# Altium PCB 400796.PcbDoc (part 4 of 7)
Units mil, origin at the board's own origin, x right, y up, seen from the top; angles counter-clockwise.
Board outline 2086.61 x 2086.61 mil, 6 copper layers (Top Layer, Mid Layer 1, Mid Layer 2, Mid Layer 3, Mid Layer 4, Bottom Layer), stack 58.818 mil thick; 313 components, 234 nets, 1244 pads, 2538 vias.
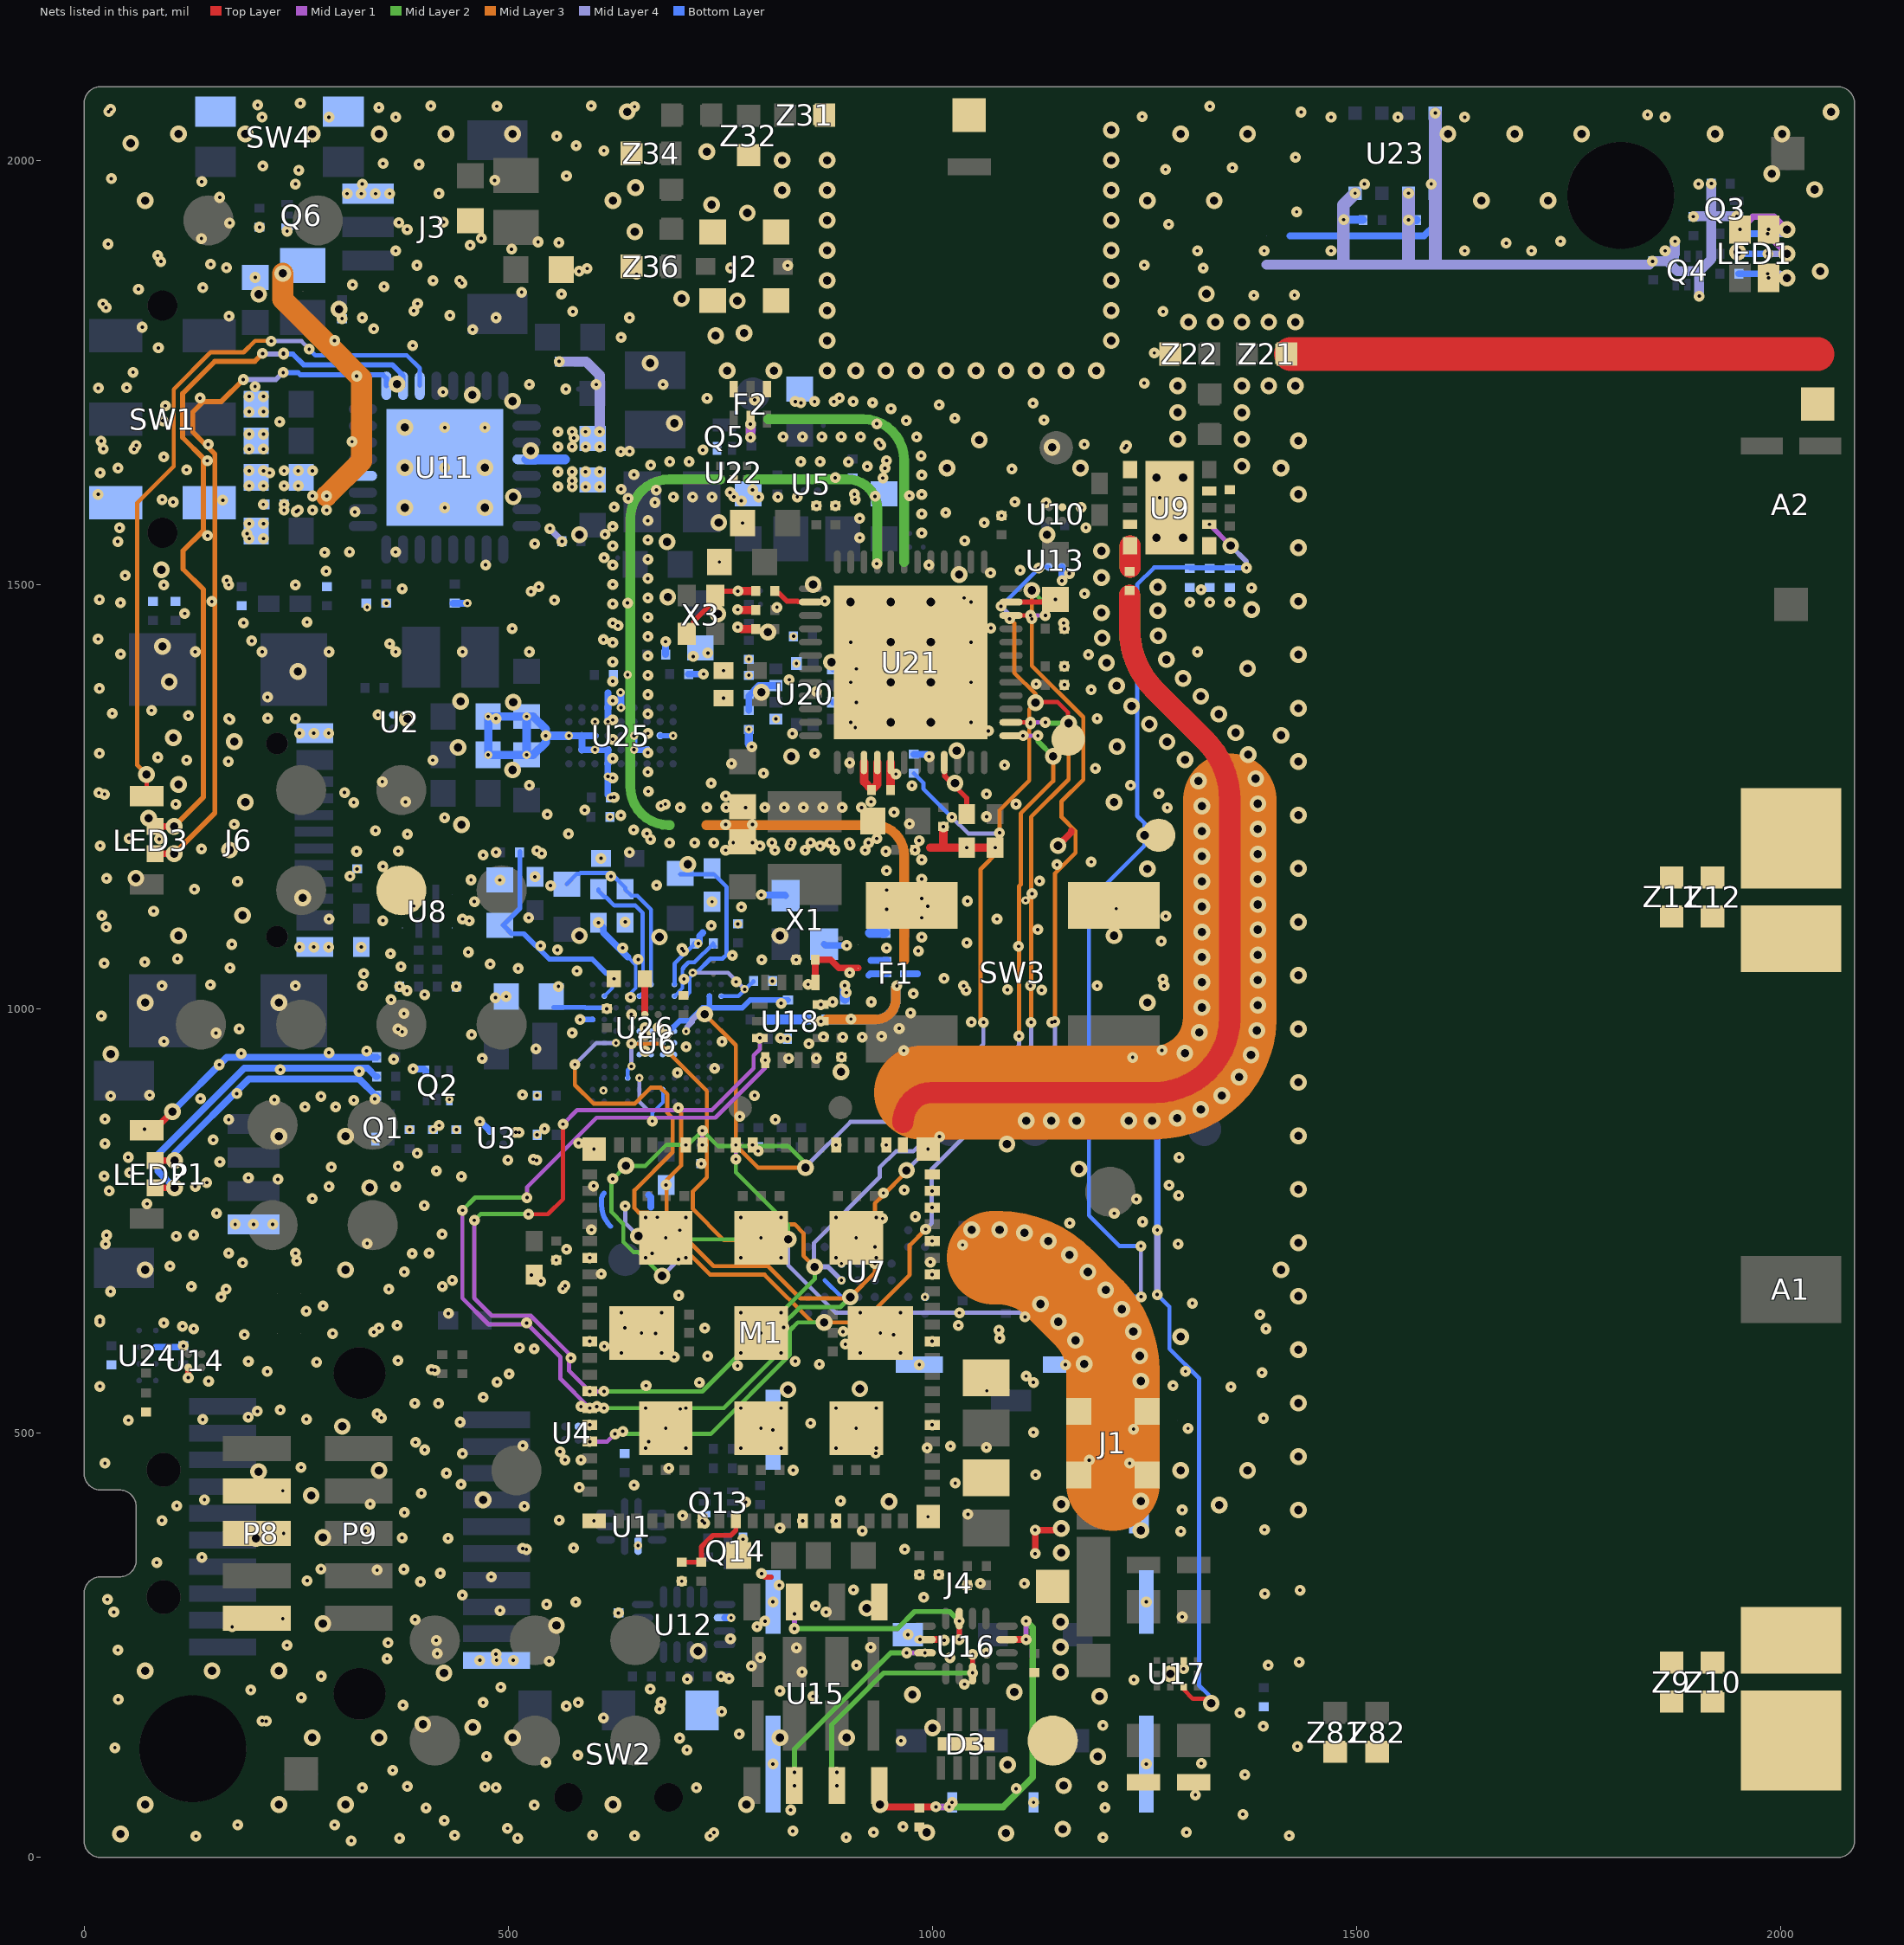
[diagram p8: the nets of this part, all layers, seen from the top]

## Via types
v1: diameter 12.8, hole 3.94, Mid Layer 4 to Bottom Layer, tented both sides, 653 vias
v2: diameter 12.8, hole 3.94, Top Layer to Mid Layer 1, tented both sides, 560 vias
v3: diameter 12.8, hole 3.94, Mid Layer 3 to Mid Layer 4, tented both sides, 388 vias
v4: diameter 19.68, hole 9.84, Mid Layer 1 to Mid Layer 4, tented both sides, 311 vias
v5: diameter 12.8, hole 3.94, Mid Layer 1 to Mid Layer 2, tented both sides, 265 vias
v6: diameter 19.68, hole 9.84, Top Layer to Bottom Layer, tented both sides, 169 vias
v7: diameter 9.84, hole 3.94, Mid Layer 4 to Bottom Layer, tented both sides, 105 vias
v8: diameter 12.8, hole 3.94, Top Layer to Mid Layer 1, tented top, 70 vias
v9: diameter 9.84, hole 3.94, Top Layer to Mid Layer 1, tented both sides, 17 vias

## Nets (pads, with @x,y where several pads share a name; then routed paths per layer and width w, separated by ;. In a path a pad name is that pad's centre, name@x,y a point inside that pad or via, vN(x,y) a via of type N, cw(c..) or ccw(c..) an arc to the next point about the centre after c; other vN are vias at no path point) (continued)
GND: C1.2 C2.2 C3.2 C4.2 C5.2 C6.2 C7.2 C8.1 C10.2 C11.1 C12.2 C13.2 C14.1 C15.2 C16.2 C17.1 C18.2 C19.2 C20.2 C21.2 C22.1 C23.1 C24.1 C25.1 C26.2 C27.2 C28.2 C29.1 C30.1 C32.1 C33.1 C34.1 C35.1 C36.1 C37.1 C38.1 C39.1 C40.1 C41.1 C42.1 C43.1 C44.1 C45.2 C46.1 C49.1 C50.1 C51.1 C54.2 C55.2 C56.1 C57.1 C58.1 C59.1 C60.1 C61.1 C62.2 C63.1 C64.1 C65.1 C66.2 C67.2 C68.1 C69.1 C70.1 C71.1 C72.1 C73.1 C75.1 C76.1 C77.1 C78.1 C79.2 C80.1 C81.1 C82.2 C83.2 C84.2 C85.2 C86.1 C87.1 C88.1 C89.1 C90.1 C91.1 C92.1 C93.1 C94.1 C95.1 C96.1 C97.1 C98.1 C99.2 C100.2 C101.1 C102.1 C103.1 CR1.1 D3.9 F1.2 F1.3 F1.5 F2.2 F2.5 F2.7 J1.2 J2.2 J3.1 J4.0 J4.C5 J4.CSW J6.A1 J6.A12 M1.1 M1.7 M1.13 M1.15 M1.20 M1.25 M1.30 M1.34 M1.36 M1.38 M1.39 M1.40 M1.41 M1.43 M1.46 M1.51 M1.55 M1.60 M1.66 M1.71 M1.76 M1.105 M1.106 M1.107 M1.108 M1.109 M1.110 M1.111 M1.112 M1.113 NT1.1 NT2.1 P1.1 P8.3 P8.5 P8.9 P9.20 Q1.2 Q2.1 Q2.4 Q3.2 Q4.1 Q4.4 Q5.2 Q6.1 Q13.1 Q14.2 R7.2 R8.2 R9.1 R11.1 R15.2 R30.1 R33.1 R38.1 R41.1 R42.1 R44.1 R45.1 R46.1 R53.1 R54.1 R58.2 R59.2 R60.1 R61.2 R64.2 SBI2.2 SW1.1 SW1.4 SW2.1 SW3.1 SW4.2 TP15.1 TP16.1 U1.6 U2.B1 U3.B1 U4.B1 U5.B1 U6.A5 U6.B2 U6.B9 U6.C2 U6.D12 U6.E5 U6.E6 U6.E7 U6.E8 U6.F5 U6.F6 U6.F7 U6.F8 U6.G5 U6.G6 U6.G7 U6.G8 U6.K6 U6.K11 U7.A2 U7.D5 U7.F4 U8.5 U8.8 U9.1 U9.4 U9.6 U9.9 U9.11 U10.B1 U11.33 U12.6 U13.B1 U14.B1 U15.1 U16.6 U17.7 U18.6 U18.7 U20.1 U20.3 U20.7 U20.11 U21.27 U21.28 U21.47 U21.49 U22.2 U23.1 U23.5 U23.7 U24.B1 U25.A3 U25.B3 U25.C2 U25.D2 U25.D3 U25.E5 U25.F1 U25.F2 U25.F4 U25.F5 U25.G2 U25.G3 U25.G4 U25.H2 U25.H3 U25.J3 U26.B1 U26.B2 U26.C3 X1.2 X1.4 X3.2 X3.4 Z6.2 Z22.2 Z32.1 Z34.2 Z36.2 | length 6211.1
  Top Layer w6: X3.4@710.43,1441.93 718.26,1449.76 718.26,1456.47 736.07,1474.28 736.07,1479.38 749.01,1492.31 v2(770.65,1492.31) ; 798.97,333.54 802.25,330.26 809.75,330.26 ; U21.47@1092.52,1479.33 1141.73,1479.33 v2(1144.68,1482.28)
  Top Layer w6.69: v2(122.81,565.43) U14.B1@122.81,577.34
  Top Layer w7.87: U16.6@991.14,256.89 v2@1013.78,256.89 ; v2(1121.06,358.09) v2(1121.06,385.83) v2(1151.77,385.83) ; v6(1147.88,1192.29) 1163.39,1207.8 1163.39,1209.65
  Top Layer w9.84: v2@770.43,1469.99 C70.1@791.73,1469.99 ; v2(770.65,1492.31) 770.88,1492.55 C69.1@791.73,1492.55 ; v2@771.56,1450.95 775.07,1447.43 C71.1@791.73,1447.43 ; C64.1@776.92,1238.08 C64.1@777.66,1237.34 ; 997.05,1189.96 1012.8,1189.96 ; v2@1012.8,1208.27 1012.8,1189.96 ; v2(1073.82,1189.96) 1012.8,1189.96
  Top Layer w10: U21.27@919.29,1290.35 919.29,1267.56 928.1,1258.75 C66.2@928.1,1258.35 ; C66.2@928.1,1257.76 C66.2@928.1,1258.35 ; U21.28@935.04,1290.35 935.04,1264.7 929.01,1258.67 928.42,1258.67 C66.2@928.1,1258.35
  Mid Layer 1 w11.81: v2(785.43,1673.23) v5(785.43,1688.98)
  Mid Layer 2 w11.42: 690.37,1216.54 689.05,1216.54 cw(c689.05,1261.74) 643.84,1261.74 643.84,1577.85 cw(c690.01,1577.85) 690.01,1624.02 750,1624.02 ; 782.48,1624.02 899.61,1624.02 cw(c899.61,1588.58) 935.04,1588.58 935.04,1526.57 ; 806.1,1694.88 918.28,1694.88 cw(c918.28,1646.63) 966.54,1646.63 966.54,1526.57
  Mid Layer 3 w11.42: 733.14,1216.54 931.09,1216.54 cw(c931.09,1181.1) 966.53,1181.1 966.53,1057.11 ; 875.24,987.41 933.22,987.41 ccw(c933.22,1010.85) 956.67,1010.85 956.67,1025.61
  Mid Layer 3 w25.12: 965.25,869.54 965.25,866.12 cw(c1001.58,866.12) 975.89,891.81 ; 1189.72,405.31 1203.3,418.89 ccw(c1180.85,441.34) 1212.6,441.34 ; 1232.28,1487.4 1232.28,1446.93 ; 1232.78,1520.67 1232.78,1545.53 ; 1232.28,1446.93 ccw(c1332.28,1446.93) 1261.57,1376.22 ; 1232.28,1446.93 ccw(c1332.28,1446.93) 1261.57,1376.22 ; 1261.57,1376.22 1321.1,1316.69 ; 1321.1,1316.69 cw(c1250.39,1245.98) 1350.39,1245.98 ccw(c1250.39,1245.98) 1321.1,1316.69
  Mid Layer 3 w110.24: 986.5,901.33 1261.45,901.33 ccw(c1261.45,990.9) 1324.78,927.57 ccw(c1262.96,989.39) 1350.39,989.39 1350.39,1245.98 ; 1071.74,706.64 1078.2,706.64 cw(c1078.2,606.64) 1148.91,677.35 1183.31,642.96 cw(c1112.6,572.24) 1212.6,572.24 1212.6,439.83
  Mid Layer 4 w4.92: v3(761.44,1608.56) 772.63,1597.37 773.45,1597.37 v1(774.71,1598.63)
  Mid Layer 4 w11.81: 1393.7,1876.97 1844.62,1876.97 v1(1848.56,1880.9) 1866.15,1880.9 ; v1(1875,1904.53) 1875,1889.76 1866.15,1880.9 ; v1@1897.24,1934.05 1917.91,1934.05 ; v1(1903.54,1839.77) 1903.54,1869.09 ; v1(1917.91,1972.44) 1917.91,1934.05 ; v1(1947.83,1934.05) 1917.91,1934.05 ; 1866.15,1880.9 1877.95,1869.09 1903.54,1869.09 ; 1903.54,1869.09 1917.91,1883.46 1917.91,1934.05
  Mid Layer 4 w15: 1484.13,1881.89 1484.13,1947.18 v1(1498.03,1961.08) ; 1561.02,1879.57 v1(1561.02,1929.6) v1(1561.02,1961.08) ; 1592.52,1879.92 v1(1592.52,2055.57)
  Bottom Layer w4.13: U6.B9@640.73,1014.96 650.28,1024.51 650.28,1051.68 640.94,1061.02 ; v1(669.81,867.68) 669.81,877.58 682.07,889.84 U6.K6@682.07,904.72
  Bottom Layer w4.92: U6.A5@695.85,1028.74 695.95,1028.84 695.95,1053.25 719.08,1076.38 C28.2@719.08,1076.97 ; v1(731.3,394) Q13.1@731.3,404.53
  Bottom Layer w5: 873.03,680.12 892.72,660.43
  Bottom Layer w5.91: U25.B3@678.94,1321.85 v7(694.29,1321.85) U25.A3@694.56,1322.12
  Bottom Layer w6: 613.02,782.73 ccw(c620.45,775.29) 609.94,775.29 609.94,769.29 ccw(c646.05,769.29) 620.51,743.76
  Bottom Layer w6.69: v1(584.63,987.4) U6.D12@599.39,987.4 ; v1@688.96,969.69 688.96,972.85 702.13,986.01 714,986.01 729.16,1001.18 U6.C2@737.19,1001.18 ; U6.B2@737.19,1014.96 U6.C2@737.19,1001.18 ; C24.1@829.71,1010.43 785.07,1010.43 775.81,1001.18 U6.C2@737.19,1001.18
  Bottom Layer w7.87: U24.B1@84.65,601.38 115.75,601.38 v1(117.13,602.76) ; v1(387.8,929.13) 400.41,929.13 Q2.1@403,926.55 ; C79.2@435.04,1477.95 v7(451.77,1477.95) ; v1(466.54,867.13) 467.52,867.13 U3.B1@478.35,856.3 ; v7(571.46,1321.85) U25.H3@586.81,1321.85 ; U25.G3@602.17,1321.85 U25.H3@586.81,1321.85 ; v1(606.28,1101.57) 612.19,1095.67 612.19,1089.77 640.94,1061.02 ; U25.F1@617.37,1288.63 617.37,1252.12 v7(620.47,1249.02) ; U25.F1@617.52,1288.78 U25.F2@617.52,1305.32 v7(602.17,1305.32) U25.H2@586.81,1305.32 U25.H3@586.81,1321.85 ; v7(617.52,1338.39) U25.F5@617.52,1354.92 617.52,1372.64 ; v7(632.87,1354.92) v7@632.87,1372.32 ; v7(648.23,1321.85) v7(648.23,1305.32) U25.C2@663.58,1305.32 ; 665.53,780.64 668.01,778.16 668.01,766.49 ; R9.1@685.43,1417.32 v1(685.43,1432.68) ; C85.2@712.46,1394.5 v1(730.13,1394.5) ; v7(724,1076.97) 725.38,1078.35 725.38,1085.83 729.31,1089.76 ; U12.6@754.92,282.48 755.02,282.38 v7(762.63,282.38) ; v1(798.21,1134.2) 826.04,1134.2 X1.2@826.96,1133.28 ; U5.B1@864.61,1625.93 v1@886.26,1625.93 ; X1.4@872.23,1076.19 873.82,1074.61 v1(898.97,1074.61) ; U20.3@883.27,1361.22 v1(910.43,1361.22) ; U20.1@883.27,1400.59 v1(910.43,1400.59) ; 924.76,1039.41 926.71,1041.36 F1.2@946.84,1041.36 ; 927.37,1057.13 F1.3@945.57,1057.13 ; CR1.1@943.11,1089.61 CR1.1@946.01,1089.61 ; F1.3@945.59,1057.11 F1.3@946.84,1057.11 ; F1.5@966.53,1041.36 982.39,1041.36 ; R53.1@978.01,1299.93 993.38,1299.93 v1(996.06,1297.24) ; v7@1108.8,1127.81 v7(1109.65,1127.81) ; v1(1152.56,1504.52) U13.B1@1152.56,1520.8 ; Q4.4@1875.98,1886.81 v1@1875.98,1903.54 ; v1(1903.54,1839.77) Q4.1@1903.54,1853.35
  Bottom Layer w9.84: C80.1@521.65,1299.32 v7(521.65,1299.21) ; v7(571.46,1321.85) v1(544.19,1321.85) ; v1@1561.04,1929.58 C56.1@1570.43,1929.58 ; v7(521.65,1299.21) 529.53,1299.21 544.19,1313.87 v1(544.19,1321.85) ; v7(521.65,1299.21) v7(476.38,1299.21) v7(476.38,1344.49) v7(521.65,1344.49) ; v7(521.65,1299.21) v7(521.65,1344.49) ; v7(521.65,1344.49) 529.53,1344.49 544.19,1329.83 v1(544.19,1321.85)
  Bottom Layer w10: v7(783.46,1329.33) 783.46,1312.37 v1(787.02,1308.81) ; v1(1484.61,1929.9) C57.1@1507.17,1929.9
  Bottom Layer w11.81: C25.1@896.64,1011.81 v1(896.65,1027.56) ; 926.38,1089.61 CR1.1@943.11,1089.61
  other v1: 314.96,19.68 898.25,23.79 1420.28,25.59 436.84,26.19 599.39,26.19 742.29,29.31 1299.21,29.53 181.1,38.39 295.28,38.39 1023.03,64.96 1119.09,64.96 1309.78,73.7 363.83,102.63 812.01,110.24 1251.97,110.24 1316.77,110.88 544.42,112.12 1430.12,130.91 772.08,145.38 1389.76,154.53 1362.2,170.28 678.32,174.91 582.47,182.6 256.02,188.46 491.14,200.79 1237.23,209.48 846.27,218.62 786.42,225.39 910.43,226.38 1395.65,226.48 1432.09,230.32 548.23,231.3 466.54,232.28 486.22,232.28 505.91,232.28 416.34,240.16 971.06,262.6 390.09,280.29 1294.29,283.46 629.92,288.19 862.18,296.5 545.28,298.23 579.47,301.04 812.01,301.18 1251.97,301.18 27.56,304.13 1391.63,310.91 906.81,315.26 1433.07,314.96 419.85,334.98 345.47,338.58 279.24,339.96 85.63,347.44 776.57,375 374.9,376.61 429.13,375.98 1292.62,384.25 331.69,384.84 917.32,384.84 1391.26,386.2 560.02,397.65 705.51,402.92 1294.29,409.45 109.25,414.37 583.77,436 427.17,452.76 689.22,458.75 24.61,464.57 1232.28,464.57 566.93,468.5 585.63,468.5 1184.7,468.1 933.07,476.38 401.57,480.32 665.35,490.16 812.01,503.94 1236.89,504.64 856.3,511.81 52.4,515.25 1389.99,517.55 345.47,522.64 231.38,527.35 702.76,528.54 585.63,531.5 604.33,531.5 470.47,542.32 18.7,555.12 662.4,556.1 1283.46,556.1 146.81,561.38 1110.36,567.33 500.98,569.88 1388.23,571.31 409.45,574.8 984.45,580.71 1156.68,580.71 838.17,584.74 573.82,588.58 695.57,589.71 530.51,599.41 613.19,602.36 897.19,604.86 188.98,616.14 341.54,619.09 637.57,624.25 116.14,625.98 369.09,626.97 1030.51,626.97 521.65,629.92 18.7,630.91 1385.97,639.62 1306.29,653.06 161.42,660.43 564.17,670.33 538.39,679.13 434.06,680.12 101.38,696.85 187.01,700.79 997.46,701.62 386.81,711.61 669.44,711.97 1035.43,721.85 333.66,723.43 1289.42,722.95 26.57,733.27 129.26,733.66 598.07,739.64 702.34,739.13 178.15,746.06 199.8,746.06 222.44,746.06 941.1,752.94 675.66,754.46 979.66,755.19 1214.2,759.01 400.99,768.39 74.25,770.23 1240.32,775.64 1290.14,780.12 942.19,783.04 966.73,786.36 686.01,792.52 144.68,795.28 623.12,799.72 23.78,802.91 291.48,813.39 370.32,814.39 727.38,817.52 529.42,822.73 52.09,825.07 1290.58,824.96 794.64,832.4 152.23,845.62 512.8,854.33 71.34,858.24 24.61,870.08 224.41,892.72 317.96,892.24 516.79,898.82 830.59,941.68 863.13,941.68 1235.92,942.78 661.4,950 688.96,950 966.12,950.73 1270.34,951.06 854.31,958.86 894.31,966.67 917.11,966.67 871.52,966.95 939.88,967.64 456.69,969.49 661.4,969.69 685.96,969.69 960.73,976.87 377.05,994.5 974.1,995.33 882.31,1008.14 927.9,1008.14 361.85,1010.8 497.52,1014.47 977.4,1017.88 1039.7,1021.83 1088.33,1022.61 1128.59,1022.08 372.03,1026.38 438.65,1026.38 853.33,1028.74 1271.46,1034.89 1013.66,1035.81 329.72,1041.34 361.22,1064.96 452.89,1066.8 704.72,1070.87 945.8,1071.66 634.84,1071.85 253.94,1072.83 270.87,1072.83 288.39,1072.83 326.77,1072.83 1101.4,1073.63 1040.48,1077.91 1269.68,1079.72 987.26,1084.49 1124.02,1093.5 739.31,1097.95 637.8,1102.36 454.06,1103.74 352.27,1103.91 987.26,1107.29 945.8,1117.25 1216.54,1118.11 774.65,1119.98 460.08,1126.3 740.14,1126.18 1041.21,1126.97 987.26,1130.08 945.8,1140.05 1126.06,1150.53 456.12,1151.99 490.14,1151.77 987.26,1152.88 531.48,1155.71 945.8,1162.84 352.17,1167.8 1146.65,1169.96 987.26,1175.68 609.23,1177.36 470.32,1181.13 539.37,1183.07 321.24,1185.61 945.1,1185.63 370.31,1185.94 719.55,1195.81 742.34,1195.81 765.14,1195.81 787.93,1195.81 810.73,1195.81 833.52,1195.81 856.32,1195.81 879.11,1195.81 901.91,1195.81 924.7,1195.81 984.26,1198.27 571.09,1206.17 663.39,1206.69 972.94,1218.06 425.06,1225.27 1063.71,1226.44 954.63,1231.64 733.96,1237.27 756.76,1237.27 779.55,1237.27 802.35,1237.27 825.15,1237.27 847.94,1237.27 870.74,1237.27 893.53,1237.27 916.33,1237.27 685.04,1241.14 1098.43,1241.21 1266.73,1253.94 307.09,1254.92 739.17,1265.75 956.95,1276.69 800.83,1277.51 1191.93,1283.46 1084.86,1287.23 861.22,1301.18 253.94,1324.8 270.87,1324.8 288.39,1324.8 1115.34,1335.99 216.54,1342.52 346.46,1346.46 1187.01,1375.98 1122.15,1382.72 717.97,1415.25 1183.68,1417.29 735.24,1419.25 360.24,1430.12 612.2,1435.04 629.33,1451.38 187.99,1454.72 1154.55,1454.65 262.8,1455.71 1117.13,1459.65 816.62,1473.21 43.02,1478.51 1303.15,1478.94 1326.77,1478.94 1350.39,1478.94 150.6,1479.94 873.07,1480.43 1037.4,1484.25 1179.1,1489.11 375,1495.08 1375.98,1496.06 94.03,1499.44 168.31,1504.92 285.43,1515.75 1103.35,1516.73 612.94,1531.5 283.51,1537.75 312.99,1538.39 39.79,1550.65 194.64,1554.13 211.47,1554.13 145.69,1557.55 1180.73,1567 194.64,1571.85 211.47,1571.85 1061.02,1572.83 1015.54,1584.75 425.2,1590.55 211.34,1594.38 1133.92,1596.28 92.14,1600.01 972.77,1604.62 907.94,1606.5 787.9,1611.45 194.64,1616.33 211.47,1616.33 885.38,1625.93 19.09,1631.71 194.64,1634.05 211.47,1634.05 1093.51,1636.08 943.93,1637.15 425.2,1637.8 145.42,1645.96 94,1650.3 729.33,1658.46 58.98,1659.59 194.64,1659.54 211.47,1659.54 22.77,1659.79 1178.9,1665.2 194.64,1677.26 211.47,1677.26 425.2,1685.04 472.44,1685.04 934.32,1689.45 92.91,1693.06 1131.33,1693.87 1026.27,1695.85 194.64,1703.74 211.47,1703.74 734.33,1719.49 194.64,1721.46 211.47,1721.46 567.91,1730.32 295.28,1787.4 341.54,1801.26 304.16,1813.32 431.25,1817.02 393.11,1830.98 353.65,1851.05 316.49,1853.21 442.66,1858.18 201.8,1861.89 651.16,1865.77 583.44,1869.14 167.88,1873.21 392.37,1876.17 86.84,1887.64 535.11,1903.7 138.38,1907.63 468.23,1907.92 239.34,1916.43 380.91,1918.31 206.85,1921.04 171.64,1925.99 1896.65,1933.46 159.91,1956.23 310.04,1960.63 326.77,1960.63 343.5,1960.63 360.24,1960.63 418.25,1960.84 483.97,1976.2 568.55,1981.54 252.95,1988.19 210.63,1993.11 394.81,1994.99 352.36,1996.06 612.66,2011.25 557.06,2028.27 31.5,2060.04 347.44,2062.01 486.5,2063.59 648.91,2063.03 408.66,2063.87 597.77,2064.15 204.72,2064.96 254.92,2066.93
  other v2: 371.84,22.76 511.01,22.76 1200.79,23.62 131.96,25.2 648.84,25.6 737.72,25.28 930.5,29.66 835.42,31.13 965.26,36.26 424.62,43.46 530.74,61.74 1098.62,81.12 380.93,83.63 1200.79,83.66 474.34,119.1 581.93,120.39 962.85,137.49 702.09,140.65 1200.79,155.51 612.39,164.45 751.48,171.8 568.53,178.38 375.96,179.44 470.4,182.61 680.13,183.44 40.31,186.17 196.57,197.4 710.9,210.18 760.22,210.73 279.53,213.58 1280.25,216.52 1151.02,218.39 1295.98,222.44 1151.02,247.92 239.17,250 358.27,252.95 1013.78,255.91 761.86,257.68 1151.02,277.44 234.25,281.5 35.13,289.24 490.3,291.07 445.87,309.06 1040.94,320.87 1108.27,322.83 396.65,324.8 704.55,325.49 984.59,333.18 1007.22,333.18 376.97,339.57 769.62,355.94 1151.77,359.14 235.24,381.89 600.9,396.65 728.84,396.65 846.95,396.65 886.14,396.65 994.61,401.57 377.62,406.42 1151.77,416.22 397.64,429.13 234.25,432.09 444.35,439.68 1121.52,450.84 255.91,459.65 560.97,478.18 661.86,482.22 709.24,482.22 774.07,482.22 821.44,482.22 886.27,482.22 933.65,482.22 390.75,489.17 1119,500.99 1301.15,505.57 685.55,505.91 797.76,505.91 909.96,505.91 595.98,509.84 999.53,509.84 139.88,516.18 262.12,516.47 350.61,518.03 193.56,519.02 661.86,529.59 709.24,529.59 774.07,529.59 821.44,529.59 886.27,529.59 933.65,529.59 389.74,535.26 1119,559.74 216.05,572.7 1298.09,572.92 370.08,585.63 633.32,594.42 680.69,594.42 774.07,594.42 821.44,594.42 914.82,594.42 962.19,594.42 513.43,600.62 595.98,608.27 999.53,608.27 293.09,617.4 657.01,618.11 797.76,618.11 938.5,618.11 1078.21,621.48 129.27,622.97 1392.98,623.12 94,629.8 18.74,633.37 429.37,641.1 1031.78,641.69 633.32,641.8 680.69,641.8 774.07,641.8 821.44,641.8 914.82,641.8 962.19,641.8 31.28,666.97 167.55,669.55 126.56,672.89 422.23,673.06 566.88,673.76 999.53,687.01 377.49,689.97 556.61,703.94 595.98,706.69 661.86,706.63 709.24,706.63 774.07,706.63 821.44,706.63 886.27,706.63 933.65,706.63 25.4,722.83 999.53,726.38 685.55,730.32 797.76,730.32 909.96,730.32 108.66,732.18 422.14,734.42 1161.68,747.56 1247.55,749.1 661.86,754 709.24,754 774.07,754 821.44,754 886.27,754 933.65,754 156.3,759.21 999.53,765.75 29.54,785.34 999.53,785.43 1278.95,792.19 228.57,799.1 444.72,802.45 53.78,806.81 415.35,809.06 160.05,819.71 392.72,829.81 600.9,834.65 994.61,834.65 709.17,839.57 787.91,839.57 886.34,839.57 945.39,839.57 24.69,841.22 508.75,854.54 542.75,858.73 1110.41,868.3 1140.09,868.3 1169.78,868.3 1231.15,868.3 1258.83,868.3 1288.38,871.2 1316.24,881.44 260.5,884.41 296.57,884.41 31.41,897.43 1340.97,897.87 180.08,900.14 1361.2,919.59 699.37,924.68 231.37,928.28 743.2,929.81 159.51,934.23 892.87,943.25 1375.34,945.69 1297.43,947.62 333,950.48 709.76,955.16 94.2,961.66 751.88,961.4 820.9,965.74 1314.28,972.06 1382.3,974.55 182.84,976.4 660.95,977.61 676.7,977.61 1045.88,984.34 1140.68,984.03 868.33,985.38 903.9,988 645.2,993.35 616.14,1000.05 1317.36,1001.59 1383.43,1004.21 868.33,1005.06 821.58,1006.5 644.06,1013.59 898.47,1019.12 559.12,1026.36 149.02,1028.23 1317.36,1031.27 768.64,1031.89 1383.43,1033.89 624.53,1035.48 707.05,1035.02 580.92,1044.68 373.48,1049.89 478.69,1052.69 653.06,1058.2 798.71,1057.91 839.38,1057.92 1317.36,1060.96 764.1,1062.96 1383.43,1063.58 706.66,1068.04 983.35,1068.27 557.92,1069.41 174.31,1075.96 1317.36,1090.64 1383.43,1093.26 26.05,1096.48 1317.36,1120.33 1383.43,1122.95 549.8,1145.26 674.76,1145.58 1317.36,1150.01 1383.43,1152.63 26.54,1153.69 313.41,1156.17 621.04,1156.08 1317.36,1179.7 1383.43,1182.32 533.66,1186.55 756.25,1186.9 814.32,1186.9 849.76,1186.9 885.19,1186.9 920.62,1186.9 979.33,1187.01 1040.35,1189.96 796.61,1191.82 832.04,1191.82 867.47,1191.82 902.91,1192.8 690.1,1195.81 667.65,1199.75 934.4,1200.68 53.04,1200.85 381.11,1205.76 1317.36,1209.38 647.77,1210.9 1383.43,1212 1012.8,1214.56 756.25,1217.17 787.75,1217.17 632.65,1227.97 702.74,1237.27 680.01,1239.02 1317.36,1239.07 1383.43,1241.69 317.86,1243.18 927.51,1243.98 624.66,1249.31 756.25,1250.87 24.13,1252.82 665.11,1256.28 1313.28,1268.47 1380.89,1271.27 623.11,1272.06 664.57,1279.07 1297.48,1293.6 623.11,1294.85 1371.93,1299.57 664.57,1301.86 1276.49,1314.59 623.11,1317.65 664.57,1324.66 1357.2,1325.34 1255.5,1335.58 903.54,1337.6 1045.28,1337.6 623.11,1340.44 664.57,1347.45 1337.22,1347.29 33.26,1348.11 1234.68,1356.74 623.11,1363.24 753.74,1366.14 1316.23,1368.29 664.57,1370.25 1217.14,1380.69 1155.43,1381.89 903.54,1384.84 1045.28,1384.84 623.11,1386.03 1295.24,1389.28 664.57,1393.04 753.74,1398.58 1155.43,1403.54 1205.11,1407.83 623.11,1408.83 1275.57,1411.51 664.57,1415.84 43.13,1417.98 623.11,1431.62 903.54,1432.09 1045.28,1432.09 1199.86,1437.04 664.57,1438.63 1265.97,1439.6 1155.43,1447.83 770.43,1449.82 623.11,1454.42 664.57,1461.43 1199.25,1466.72 1265.32,1469.28 770.43,1470.42 623.11,1477.21 1045.28,1479.33 664.57,1484.22 623.11,1500.01 664.57,1507.02 1199.25,1508.09 48.48,1510.58 623.11,1522.81 748.82,1526.57 664.57,1529.81 1199.25,1539.58 623.11,1545.6 531.18,1548.16 664.57,1552.61 1037.91,1551.77 914.31,1555.08 192.12,1559.84 987.27,1560.55 623.11,1568.4 776.1,1572.44 664.57,1575.4 914.31,1577.87 1291.34,1578.74 1081.42,1581.11 987.27,1583.35 250.29,1585.96 624.76,1591.13 863.19,1592.92 885.63,1592.92 672.8,1596.67 908.83,1600 1267.72,1602.36 694.61,1603.29 717.4,1603.29 740.2,1603.29 765.75,1603.35 795.09,1603.29 817.89,1603.29 840.68,1603.29 987.27,1606.14 632.93,1612.41 941.45,1625.54 648.1,1629.42 987.27,1628.94 218.83,1631.66 120.89,1635.22 40.17,1637.01 923.14,1639.12 667.96,1640.62 690.38,1644.75 713.17,1644.75 844.66,1644.75 867.46,1644.75 900.98,1644.47 945.81,1646.07 986.72,1651.72 936.85,1667.04 577.32,1672.73 824.01,1674.15 846.81,1674.15 869.6,1674.15 892.4,1674.15 915.19,1674.15 981.17,1673.84 968.98,1693.1 951.07,1707.2 95.96,1710.61 929.4,1714.27 838.26,1715.61 861.05,1715.61 883.85,1715.61 906.65,1715.61 50.26,1731.98 87.65,1778.87 25.92,1826.35 562.7,1842.19 592.97,1872.29 455.13,1899.79 559.58,1902.73 371.11,1926.53 423.67,1927.06 580.1,2017.24
  other v3: 499.05,34.38 1365.74,50.84 832.88,56.01 403.09,58.37 1203.19,58.69 472.47,83.38 1368.13,97.5 710.54,126.79 36.38,129.37 214.75,160.67 667.47,198.57 1037.67,204.19 750.73,213.46 357.14,234.27 1063.32,240.88 39.9,244.37 793.18,272.01 989.65,306.56 1056.31,323.05 798.5,334.6 521.35,363.03 967.21,363.14 820.17,388.32 1041.8,404.46 519.02,413.97 337.33,416.49 648.17,438.75 835.8,456.35 1021.18,484.66 517.23,485.36 635.02,502.17 204.3,525.81 725.28,559.63 770.22,579.43 274.2,583.73 193.74,584.58 734.85,590.86 1079.21,611.88 954.22,615.98 673.64,617.38 731.6,623.83 824.62,624.63 261.93,643.93 700.86,662.38 359.22,669.61 609.66,687.6 250.8,702.99 568.65,716.71 269.08,776.29 600.54,791.32 193.7,800.8 582.93,841.82 137.25,894.17 342.71,893.8 279.23,896.95 77.3,898.25 324.3,926.51 365,940.57 185.37,947.28 894.31,966.67 917.11,966.67 871.52,966.95 939.88,967.64 155.51,971.46 370.09,976.18 960.73,976.87 20.48,991.54 974.1,995.33 882.31,1008.14 927.9,1008.14 401.35,1016.65 977.4,1017.88 172.11,1048.38 23.81,1053.63 71.57,1055.19 110.24,1059.06 945.8,1071.66 538.09,1074.42 987.26,1084.49 987.26,1107.29 21.02,1109.7 82.02,1115.22 945.8,1117.25 987.26,1130.08 945.8,1140.05 130.05,1140.79 180.98,1150.08 987.26,1152.88 945.8,1162.84 987.26,1175.68 945.1,1185.63 138.57,1188.43 19.01,1192.08 719.55,1195.81 742.34,1195.81 765.14,1195.81 787.93,1195.81 810.73,1195.81 833.52,1195.81 856.32,1195.81 879.11,1195.81 901.91,1195.81 924.7,1195.81 984.26,1198.27 88.7,1199.95 177.04,1217.48 972.94,1218.06 954.63,1231.64 733.96,1237.27 756.76,1237.27 779.55,1237.27 802.35,1237.27 825.15,1237.27 847.94,1237.27 870.74,1237.27 893.53,1237.27 916.33,1237.27 108.17,1241.1 17.57,1254.55 975.82,1262.99 763.12,1288.99 902.37,1290.01 170.14,1291.65 120.95,1293.2 87.06,1296.29 18.14,1301 834.84,1324.34 908.98,1331.44 172.08,1340.84 122.95,1345.34 79.62,1351.57 216.23,1367.22 863.18,1374.13 18.13,1377.54 831.1,1387.91 197.71,1433.57 16.63,1435.79 118.67,1465.91 640.52,1478.19 554.39,1481.57 18.13,1482.33 526.91,1491.7 995.75,1522.84 934.25,1524.57 614.12,1559.04 1096.99,1597.43 641.46,1601.4 932.3,1603.87 16.57,1606.22 674.51,1611.32 632.62,1656.62 1226.63,1660.63 61.61,1663.9 938.94,1664.12 20.22,1669.04 844.8,1714.12 790.41,1717.46 890.33,1719.68 423.09,1726.82 16.79,1731.45 1249.55,1737.34 57.75,1750.1 1261.34,1772.95 387.44,1781.49 632.92,1791.24 457.95,1800.4 68.68,1803.22 576.09,1821.73 1271.71,1821.68 22.36,1830.67 1378.72,1840.74 1426.67,1841.05 515.79,1844.39 64.18,1848.04 140.09,1849.75 445.33,1855.08 762.02,1873.12 1319.02,1872.81 829.3,1875.92 1249.48,1876.41 503.87,1895.13 28.37,1901.13 1676.16,1902.33 1740.15,1904.49 1278.38,1924.36 1429.13,1939.2 32.1,1978.28 1274.68,1989.06 1353.43,1990.96 1427.74,2003.35 1247.05,2051.3 1842.8,2053.48 1434.4,2056.7 1326.76,2063.36
  other v4: 43.06,27.7 1086.61,28.54 993.11,29.53 1153.54,33.46 229.56,62.49 308.3,62.49 780.74,62.49 938.22,62.49 1154.53,84.65 1088.58,109.25 1194.88,119.09 268.93,141.23 347.67,141.23 505.15,141.23 820.11,141.23 898.85,141.23 1000,152.56 458.19,153.49 399.34,156.98 1196.85,189.96 976.38,191.93 1096.46,194.88 1280.29,216.52 424.21,217.52 1151.02,218.39 229.56,219.97 723.53,243.14 1151.02,247.92 556.87,273.62 281.5,275.59 1151.02,277.44 922.53,293.62 1151.77,359.14 202.76,375.98 281.5,376.97 1151.77,387.68 1338.01,415.37 1151.77,416.22 948.82,419.29 470.47,421.26 267.77,426.41 205.71,454.72 347.67,456.19 1292.55,456.19 1371.29,456.19 304.33,507.93 829.72,551.18 914.37,552.17 1245.63,561.33 1178.72,581.52 1244.32,590.98 1168.4,609.36 1292.55,613.67 1236.69,619.67 1148.32,631.22 1223.1,646.06 1127.33,652.21 1204.11,668.88 1183.12,689.87 72.08,692.41 308.3,692.41 1161.46,710.17 1136.49,726.23 1108.44,735.95 1046.12,739.68 1078.99,739.62 336.61,789.37 1172.55,811.26 1087.79,840.54 229.56,849.89 308.3,849.89 1110.41,868.3 1140.09,868.3 1169.78,868.3 1231.15,868.3 1258.83,868.3 1288.38,871.2 1316.24,881.44 1340.97,897.87 1361.2,919.59 892.24,925.8 1375.34,945.69 31.5,946.85 1297.43,947.62 1314.28,972.06 1382.3,974.55 1317.36,1001.59 1383.43,1004.21 72.08,1007.37 229.56,1007.37 1253.18,1007.37 1317.36,1031.27 1383.43,1033.89 1317.36,1060.96 1383.43,1063.58 678.15,1084.72 111.45,1086.11 583.89,1086.11 820.11,1086.11 1213.81,1086.11 1317.36,1090.64 1383.43,1093.26 186.71,1110.1 1317.36,1120.33 1383.43,1122.95 257.87,1130.91 1317.36,1150.01 1383.43,1152.63 61.2,1153.93 1253.18,1164.85 711.61,1170.28 1317.36,1179.7 1383.43,1182.32 171.48,1187.15 1317.36,1209.38 1383.43,1212 444.77,1216.89 76.22,1224.5 1317.36,1239.07 1383.43,1241.69 190.19,1243.59 1213.81,1243.59 111.45,1264.49 1026.53,1265.87 1313.28,1268.47 1380.89,1271.27 504.92,1281.5 1297.48,1293.6 833.66,1297.24 1371.93,1299.57 1028.54,1304.13 440.94,1308.07 1217.52,1309.06 1276.49,1314.59 177.17,1314.96 105.11,1319.61 1357.2,1325.34 1255.5,1335.58 380.99,1341.95 1337.22,1347.29 1234.68,1356.74 505.91,1361.22 443.9,1362.2 1316.23,1368.29 798.23,1373.11 1217.14,1380.69 100.36,1385.2 1295.24,1389.28 251.97,1397.64 880.91,1408.46 1205.11,1407.83 1275.57,1411.51 92.52,1427.17 1199.86,1437.04 1265.97,1439.6 806.1,1443.9 747.05,1465.43 1199.25,1466.72 1265.32,1469.28 1375.98,1470.47 687.99,1485.24 859.27,1499.98 1199.25,1508.09 1031.5,1511.81 91.18,1517.5 1199.25,1539.58 687.01,1550.2 583.89,1558.55 1135.07,1558.55 748.03,1572.83 505.91,1603.35 1174.44,1637.29 526.57,1657.48 1140.85,1661.76 1055.12,1670.28 695.87,1689.96 505.15,1716.03 457.68,1723.55 369,1736.22 667.32,1760.83 300.44,1824.25 770.03,1834.29 205.91,1842.04 1322.83,1842.52 2046.26,1869.09 1948.82,1891.73 781.8,1937.89 2039.54,1965.45 1989.23,1984.11 54.96,2019.92 190.19,2030.99 268.93,2030.99 347.67,2030.99 505.15,2030.99 1607.51,2030.99 2001.21,2030.99 640.11,2057.11 2059.06,2057.09
  other v5: 859.27,189.82 820.11,196.23 797.15,235.56 1020.49,235.25 839.69,247.13 927.08,247.66 415.15,255.82 174.65,271.77 802.49,278.45 874.58,289.13 819.4,320.81 262.93,326.12 479.87,330.6 138.92,353.74 517.03,364.16 576.92,364.65 779.96,418.75 891.58,420.12 141.92,421.61 1026.73,441.2 993.64,482.57 1063.52,483.1 443.21,512.93 417.71,534.91 1064.06,549.98 486.82,560.24 413.61,574.03 866.63,581.17 894.49,619.59 347.67,623.91 281.66,649.91 527.27,686.32 533.47,821.53 499.64,821.86 1008.28,849.52 418.51,862.61 814.81,869.61 772.82,873.16 790.27,897.86 469.24,941.59 532.59,953.01 575.37,971.75 374.96,973.12 484.75,1013.09 380.67,1021.4 902.32,1042.51 511.69,1047.49 524.07,1107.29 1274.88,1109.29 388.8,1121.08 994.29,1121.01 1117.3,1135.66 1187.01,1173.15 690.1,1195.81 667.65,1199.75 343.59,1209.94 647.77,1210.9 632.65,1227.97 546.05,1229.1 590.07,1234.13 702.74,1237.27 1276.64,1237 680.01,1239.02 378.92,1243.93 624.66,1249.31 1063.7,1253.13 665.11,1256.28 351.61,1267.57 623.11,1272.06 664.57,1279.07 411.01,1292.93 623.11,1294.85 664.57,1301.86 623.11,1317.65 664.57,1324.66 1065.9,1327.55 623.11,1340.44 664.57,1347.45 623.11,1363.24 664.57,1370.25 623.11,1386.03 664.57,1393.04 623.11,1408.83 664.57,1415.84 623.11,1431.62 664.57,1438.63 504.75,1447.99 1068.72,1448.62 623.11,1454.42 664.57,1461.43 623.11,1477.21 664.57,1484.22 1316.47,1493.95 536.09,1497.38 623.11,1500.01 664.57,1507.02 1068.37,1513.63 1161.24,1512.94 1125.13,1519.47 473.29,1523.2 623.11,1522.81 664.57,1529.81 367.25,1538.33 623.11,1545.6 664.57,1552.61 914.31,1555.08 987.27,1560.55 41.84,1566.62 623.11,1568.4 664.57,1575.4 914.31,1577.87 987.27,1583.35 319.29,1585.6 1175.34,1590.67 624.76,1591.13 672.8,1596.67 105.09,1597.21 163.47,1599.29 908.83,1600 694.61,1603.29 717.4,1603.29 740.2,1603.29 795.09,1603.29 817.89,1603.29 840.68,1603.29 987.27,1606.14 632.93,1612.41 575.36,1622.27 941.45,1625.54 987.27,1628.94 923.14,1639.12 713.17,1644.75 844.66,1644.75 867.46,1644.75 900.98,1644.47 945.81,1646.07 986.72,1651.72 1228.49,1663.63 146.47,1665.17 936.85,1667.04 315.82,1668.31 824.01,1674.15 846.81,1674.15 869.6,1674.15 892.4,1674.15 915.19,1674.15 981.17,1673.84 230.55,1691.74 968.98,1693.1 951.07,1707.2 1007.75,1711.61 1118.49,1713.56 929.4,1714.27 838.26,1715.61 861.05,1715.61 883.85,1715.61 906.65,1715.61 136.73,1719.66 201.6,1733.3 321.38,1745.6 235.07,1772.71 170.92,1816.06 388.62,1822.58 411.43,1858.12 149.22,1877.33 90.63,1880.71 138.68,1974.71 29.09,2057.33
  other v6: 72.08,62.49 623.26,62.49 72.08,219.97 150.82,219.97 1245.44,385.39 1431.1,409.45 1245.63,419.84 1431.1,472.44 1431.1,535.43 1431.1,598.43 1431.1,661.42 1410.66,692.41 1431.1,724.41 1431.1,787.4 1431.1,850.39 1431.1,913.39 1431.1,976.38 1431.1,1039.37 1431.1,1102.36 1431.1,1165.35 1431.1,1228.35 1431.1,1291.34 1410.66,1322.33 950.79,1337.6 998.03,1337.6 1431.1,1354.33 950.79,1384.84 998.03,1384.84 1371.29,1401.07 1431.1,1417.32 950.79,1432.09 998.03,1432.09 903.54,1479.33 950.79,1479.33 998.03,1479.33 1431.1,1480.31 1265.32,1497.08 1431.1,1543.31 1263.78,1555.12 1295.28,1555.12 377.95,1590.55 472.44,1590.55 1431.1,1606.3 1263.78,1625.98 1295.28,1625.98 1016.96,1637.29 1410.66,1637.29 377.95,1637.8 472.44,1637.8 1364.73,1639.55 1431.1,1669.29 1288.81,1671.23 1364.73,1671.05 377.95,1685.04 1288.81,1702.72 1364.73,1702.54 1288.81,1734.22 1364.73,1734.04 1396.23,1734.04 1427.72,1734.04 757.87,1751.97 812.99,1751.97 875.98,1751.97 909.45,1751.97 944.88,1751.97 980.31,1751.97 1015.75,1751.97 1051.18,1751.97 1086.61,1751.97 1122.05,1751.97 1157.48,1751.97 1192.91,1751.97 875.98,1787.4 1210.63,1787.4 744.41,1793.18 777.99,1796.25 1301.74,1809.27 1333.23,1809.27 1364.73,1809.27 1396.23,1809.27 1427.72,1809.27 875.98,1822.84 1210.63,1822.84 704.3,1836.82 875.98,1858.27 1210.63,1858.27 875.98,1893.7 1210.63,1893.7 649.21,1915.78 875.98,1929.13 1210.63,1929.13 739.73,1947.54 72.08,1952.25 623.26,1952.25 1253.18,1952.25 1331.92,1952.25 1646.88,1952.25 1725.62,1952.25 822.83,1964.57 875.98,1964.57 1210.63,1964.57 649.95,1967.85 822.83,2000 875.98,2000 1210.63,2000 734.15,2010.09 111.45,2030.99 426.41,2030.99 1292.55,2030.99 1371.29,2030.99 1686.25,2030.99 1764.99,2030.99 1922.47,2030.99 1210.63,2035.43
  other v7: 652.97,367.58 991.14,660.43 892.72,699.8 932.09,719.49 343.5,846.46 534.04,851.58 383.86,857.68 411.42,857.68 438.96,857.68 430.56,893.08 534.04,897.83 612.19,903.74 829.12,964.76 811.4,1032.68 770.65,1100 321.85,1164.76 619.94,1226.19 617.37,1273.77 602.17,1338.39 815.55,1341.54 632.34,1372.85 640.75,1393.7 783.46,1393.11 839.57,1406.89 783.46,1412.01 836.22,1438.98 333.66,1473.15 356.3,1477.95
  other v8: 327.99,82.18 485.47,82.18 721.69,82.18 209.88,160.92 485.47,239.66 91.77,397.14 446.1,475.88 1351.61,554.62 170.51,712.1 249.25,712.1 406.73,712.1 131.14,790.84 288.62,790.84 367.36,790.84 170.51,869.58 288.62,948.32 91.77,1027.06 249.25,1027.06 327.99,1027.06 957.91,1027.06 1036.65,1027.06 1115.39,1027.06 1194.13,1027.06 1272.87,1027.06 288.62,1105.8 446.1,1105.8 1076.02,1105.8 485.47,1184.54 642.95,1184.54 524.84,1263.28 1233.5,1263.28 170.51,1342.02 249.25,1342.02 485.47,1342.02 1194.13,1342.02 131.14,1420.76 209.88,1420.76 288.62,1420.76 367.36,1420.76 446.1,1420.76 524.84,1420.76 1312.24,1420.76 170.51,1499.5 249.25,1499.5 642.95,1656.98 524.84,1735.72 603.58,1735.72 682.32,1735.72 327.99,1814.46 485.47,1814.46 642.95,1814.46 367.36,1893.2 1312.24,1893.2 1390.98,1893.2 1469.72,1893.2 1627.2,1893.2 1705.94,1893.2 1863.42,1893.2 249.25,1971.94 327.99,1971.94 1509.09,1971.94 1587.83,1971.94 1902.79,1971.94 209.88,2050.68 288.62,2050.68 367.36,2050.68 1469.72,2050.68 1548.46,2050.68 1627.2,2050.68 1863.42,2050.68
  other v9: 1019.68,133.86 1059.06,133.86 985.24,256.89
GPS_EN: C35.2 C36.2 M1.52 R54.2 TP24.1 U9.2 | length 1954.8
  Mid Layer 1 w4.92: v5(768.23,822.84) v2(768.23,839.57)
  Mid Layer 1 w5.91: v9(1326.28,1570.87) v4(1351.38,1545.77)
  Mid Layer 2 w4.92: v4(653.32,732.18) 657.12,728.38 v4(829.93,728.38) 829.93,745.6 768.23,807.3 v5(768.23,822.84)
  Mid Layer 4 w4.92: v1(637.8,767.72) 637.8,747.7 v4(653.32,732.18) ; v4(829.93,728.38) 829.93,697.82 885.87,641.87 924.9,641.87 1104.1,641.87 v1(1109.05,636.93) ; v1(1245.6,720.4) 1245.6,661.11 v1(1245.89,660.83)
  Mid Layer 4 w5.91: v4(1351.38,1545.77) 1370.08,1527.07 v1(1370.08,1519.68)
  Bottom Layer w4.92: v1(1109.05,636.93) 1146.34,636.93 1170.24,660.83 v1(1245.89,660.83) ; v1(1245.6,720.4) 1220.39,720.4 1184.37,756.42 1184.37,1126.86 1249.97,1192.46 v6(1249.97,1204.56) 1249.97,1218.63 1241.14,1227.45 1241.14,1500 1261.22,1520.08 R54.2@1303.15,1520.08
  Bottom Layer w5.91: R54.2@1303.74,1519.68 v1(1370.08,1519.68)
GPS_RF1: C31.2 M1.42 | length 997.4
  Top Layer w25.12: 965.25,869.54 965.25,866.12 cw(c1001.58,866.12) 975.89,891.81 cw(c998.88,868.82) 998.88,901.33 1261.45,901.33 ccw(c1261.45,990.9) 1324.78,927.57 ccw(c1262.96,989.39) 1350.39,989.39 1350.39,1245.98 ccw(c1250.39,1245.98) 1321.1,1316.69 1261.57,1376.22 cw(c1332.28,1446.93) 1232.28,1446.93 1232.28,1487.4
GPS_RF2: C31.1 U9.10 | length 24.9
  Top Layer w25.12: 1232.78,1520.67 U9.10@1232.78,1545.53
HOST_IRQ: M1.77 U6.F10 U21.46 | length 2128.9
  Top Layer w4.92: U21.46@1092.52,1463.58 v2(1115.53,1463.58)
  Mid Layer 1 w4.92: v2(595.98,490.16) 616.82,490.16 v5(625.76,499.09) ; v2(1115.53,1463.58) v5(1133.07,1463.58)
  Mid Layer 2 w4.92: v4(1117.13,1493.11) 1133.07,1477.16 v5(1133.07,1463.58)
  Mid Layer 2 w5: v5(625.76,499.09) 738.52,499.09 831.74,592.31 831.74,621.04 841.22,630.53 v4(872.23,630.53)
  Mid Layer 3 w4.92: v3(578.51,934.5) 578.51,910.26 600.37,888.41 649.22,888.41 667.89,907.08 679.62,907.08 687.5,899.2 687.5,877.34 693.78,871.06 693.78,831.2 648.75,786.17 648.75,765.06 653.88,759.93 664.8,759.93 737.94,686.79 802.06,686.79 858.32,630.53 v4(872.23,630.53) 917.13,630.53 973.13,686.53 973.13,721.45 v3(991.83,740.16) ; v4(1117.13,1493.11) 1117.13,1404.28 1177.66,1343.75 1177.66,1270.26 1152.01,1244.6 1152.01,1226.02 1168.57,1209.46 1168.57,1183.87 1144.22,1159.52 v3(1144.22,985.15)
  Mid Layer 4 w4.92: v3(578.51,934.5) 603.86,959.84 v7(626.95,959.84) ; v3(991.83,740.16) 999.06,747.38 999.06,811.3 1144.22,956.46 v3(1144.22,985.15)
ID: SB1.2 SBI2.1 TP25.1 U17.3 | length 917.9
  Top Layer w4.92: U17.3@1296,200.77 1296,197.82 1306.83,186.99 1323.1,186.99 v6(1328.43,181.66)
  Mid Layer 4 w8: v1(1264.83,663.32) 1264.96,663.45 v1(1264.96,739.38)
  Bottom Layer w4.92: v1(1264.83,663.32) 1279.18,648.98 1279.18,599.5 1314.18,564.5 1314.18,202.78 1325.61,191.35 1325.61,184.49 v6(1328.43,181.66)
  Bottom Layer w8: v1(1264.96,739.38) 1264.96,913.73 1320.47,969.25 TP25.1@1320.47,1008.07
LD1_B: LED1.3 R14.2 | length 80.4
  Mid Layer 1 w7.87: v2(1985.24,1861.22) v4(2006.89,1861.22)
  Mid Layer 4 w7.87: v1(1984.44,1866.14) 1998.77,1866.14 2003.69,1861.22 v4(2006.89,1861.22)
  Bottom Layer w7.87: R14.2@1950.2,1866.14 v1(1984.44,1866.14)
LD1_G: LED1.2 R13.2 | length 94.2
  Mid Layer 1 w7.87: v2(1985.24,1918.31) 1985.24,1911.42 v4(2006.89,1889.76)
  Mid Layer 4 w7.87: v1(1984.44,1889.76) v4(2006.89,1889.76)
  Bottom Layer w7.87: R13.2@1950.2,1889.76 v1(1984.44,1889.76)
LD1_R: LED1.1 R12.2 | length 127.3
  Mid Layer 1 w7.87: v2(1951.77,1918.31) 1967.03,1933.56 1991.63,1933.56 v4(2006.89,1918.31)
  Mid Layer 4 w7.87: v1(1984.44,1913.39) 2001.97,1913.39 ccw(c2001.97,1918.31) v4(2006.89,1918.31)
  Bottom Layer w7.87: R12.2@1950.2,1913.39 v1(1984.44,1913.39)
LD2_B: LED2.3 R21.2 | length 306.9
  Top Layer w7.87: LED2.3@73.74,857.12 82.4,857.12 v6(104.1,878.82)
  Bottom Layer w7.87: v6(104.1,878.82) 168.19,942.91 R21.2@345.08,942.91
LD2_G: LED2.2 R20.2 | length 314.4
  Top Layer w7.87: LED2.2@83.74,821.12 v6(106.74,821.12)
  Bottom Layer w7.87: v6(106.74,821.12) 106.74,829.81 194.25,917.32 324.28,917.32 343.97,897.64 R20.2@345.08,897.64
LD2_R: LED2.1 R19.2 | length 374.8
  Top Layer w7.87: LED2.1@83.74,789.12 83.79,789.07 v6(106.79,789.07)
  Bottom Layer w7.87: v6(106.79,789.07) 87.09,808.77 87.09,828.39 188.82,930.12 334.13,930.12 343.97,920.28 R19.2@345.08,920.28
LD3_B: LED3.3 U11.27 | length 849.5
  Top Layer w4.92: LED3.3@73.74,1250.82 v6(73.74,1276.1)
  Mid Layer 3 w4.92: v6(73.74,1276.1) 62.74,1287.1 62.74,1596.23 105.67,1639.16 105.67,1730.09 149.21,1773.62 188.11,1773.62 201.59,1787.11 220.29,1787.11 v3(220.65,1786.75)
  Mid Layer 4 w4.92: v3(220.65,1786.75) 256.35,1786.75 256.39,1786.8 265.41,1777.78 v1(265.41,1777.4)
  Bottom Layer w4.92: v1(265.41,1777.4) 272.79,1770.03 380.56,1770.03 395.67,1754.92 U11.27@395.67,1734.25
LD3_G: LED3.2 U11.26 | length 879.5
  Top Layer w7.87: LED3.2@83.74,1214.82 106.16,1214.82 v6(106.28,1214.94)
  Mid Layer 3 w6: v6(106.28,1214.94) 140.84,1249.5 140.84,1494.13 116.74,1518.23 116.74,1539.8 140.82,1563.87 140.82,1648.57 116.14,1673.25 116.14,1725.05 154.08,1762.99 157.11,1762.99 201.25,1762.99 v3(210.49,1772.22)
  Mid Layer 4 w6: v3(210.49,1772.22) 211.05,1771.65 234.95,1771.65 v1(235.14,1771.46)
  Bottom Layer w6: v1(235.14,1771.46) 235.33,1771.65 246.1,1771.65 258.75,1759 363.26,1759 375.98,1746.27 U11.26@375.98,1734.25
LD3_R: LED3.1 U11.25 | length 832.7
  Top Layer w7.87: LED3.1@83.74,1182.82 v6(106.28,1182.82)
  Mid Layer 3 w6: v6(106.28,1182.82) 154.22,1230.75 154.22,1653.82 128.24,1679.79 128.24,1703.23 140.63,1715.62 161.89,1715.62 v3(187.77,1741.5)
  Mid Layer 4 w6: v3(187.77,1741.5) 226.07,1741.5 234.57,1750 v1(234.81,1749.76)
  Bottom Layer w6: v1(234.81,1749.76) 252.46,1749.76 255.05,1747.17 352.16,1747.17 356.3,1743.03 U11.25@356.3,1734.25
LTE_BLE_COEX: M1.54 R53.2 TP22.1 U6.E4 U13.B2 | length 1866.7
  Top Layer w4.92: v6@1121.47,1361.74 1147.35,1361.74 1159.79,1349.3 TP22.1@1159.79,1317.77
  Mid Layer 1 w4.92: v2(728.86,839.57) v5(728.86,856.45)
  Mid Layer 2 w4.92: v4(681.33,685.27) 653.18,713.42 647.39,713.42 635.67,725.14 635.67,746.48 621.64,760.52 621.64,797.79 v4(638.82,814.97) 661.71,814.97 686.64,839.91 712.32,839.91 v5(728.86,856.45) 746.82,838.48 829.68,838.48 v4@852.3,815.86
  Mid Layer 3 w4.92: v4(731.55,993.79) 768.17,957.18 768.17,839.12 794.42,812.86 v4(850.3,812.86) ; v3(1060.02,984.03) 1056.59,987.45 1056.59,1164.46 1078.93,1186.79 v3(1078.93,1207.48) 1078.93,1233.97 1113.97,1269.01 1113.97,1353.24 v6(1121.47,1360.74) 1121.47,1370.98 1096.27,1396.18 1096.27,1454.34 v3(1090.97,1459.65)
  Mid Layer 4 w4.92: v4(681.33,685.27) v1(700.79,704.72) ; v4@852.3,815.86 903.17,866.74 968.21,866.74 1060.02,958.54 v3(1060.02,984.03) ; v1(1022.91,1225.74) 1042.05,1206.59 1078.04,1206.59 v3(1078.93,1207.48) ; v1(1080.71,1474.41) 1090.97,1464.15 v3(1090.97,1459.65)
  Mid Layer 4 w6.69: v7(709.63,973.62) 709.63,974.65 710.45,974.65 710.45,978.39 716.59,984.52 716.59,986.4 723.98,993.79 v4(731.55,993.79)
  Bottom Layer w4.92: R53.2@978.01,1277.49 989.25,1266.25 989.25,1259.39 v1(1022.91,1225.74) ; v1(1080.71,1474.41) 1127.1,1520.8 U13.B2@1136.81,1520.8
MFF_1V8: C59.2 U15.8 U16.15 | length 434.7
  Top Layer w7.87: U15.8@937.2,68.9 937.2,65.55 943.11,59.65 980.31,59.65 v2(1003.94,59.65) ; U16.15@1087.6,256.89 v2@1112.2,256.89
  Mid Layer 1 w5.91: v2(1110.24,256.89) v5(1110.24,278.54)
  Mid Layer 1 w7.87: v2(1003.94,59.65) v5(1019.68,59.65)
  Mid Layer 2 w7.87: v5(1019.68,59.65) 1083.27,59.65 1118.11,94.49 1118.11,270.67 v5(1110.24,278.54)
MFF_CLK: U15.6 U16.7 | length 243.9
  Mid Layer 1 w5.91: v2(837.2,84.65) v5(837.2,100.39) ; v5(969.49,241.14) v9(991.14,241.14)
  Mid Layer 2 w5.91: v5(837.2,100.39) 837.2,127.56 950.79,241.14 v5(969.49,241.14)
MFF_IO: U15.3 U16.3 | length 271.1
  Top Layer w5.91: v2(1031.5,256.89) U16.3@1031.5,281.5
  Mid Layer 1 w5.91: v5(837.2,269.69) 837.3,269.78 v2(837.3,287.15) ; v2(1031.5,256.89) v5(1031.5,278.54)
  Mid Layer 2 w5.91: v5(837.2,269.69) 958.66,269.69 978.84,289.86 1020.18,289.86 v5(1031.5,278.54)
MFF_RST: U15.7 U16.11 | length 311.8
  Top Layer w5.91: U16.11@1047.24,216.54 v2(1047.24,239.17) v2@1047.24,241.14
  Mid Layer 1 w5.91: v2(887.2,84.65) v5(887.2,100.39) ; v5(1047.24,217.52) v2(1047.24,239.17)
  Mid Layer 2 w5.91: v5(887.2,100.39) 881.13,106.46 881.13,156.18 942.48,217.52 v5(1047.24,217.52)
MISO: M1.75 U6.J8 U7.D4 U18.1 U21.38 | length 2467.3
  Top Layer w4.92: U21.38@1092.52,1337.6 v2(1115.53,1337.6)
  Mid Layer 1 w4.92: v5(445.98,762.66) 445.98,659.03 476.77,628.24 522.76,628.24 561.57,589.43 561.57,563.94 v2(595.98,529.53) v5(612.78,529.53) ; v2(1115.53,1337.6) v5(1133.07,1337.6)
  Mid Layer 1 w5: v2(522.07,777.61) 522.07,789.76 566.88,834.56 591.32,859 604.07,871.76 743.96,871.76 802.88,930.67 v2(802.88,939.61)
  Mid Layer 2 w4.92: v5(445.98,762.66) 460.94,777.61 v2(522.07,777.61)
  Mid Layer 2 w5: v5(612.78,529.53) 754.1,529.53 820.82,596.25 820.82,625.34 844.08,648.6 891.37,648.6 v4(903.07,660.3)
  Mid Layer 2 w5.91: v5(1133.07,1337.6) 1134.06,1336.61 v4(1160.43,1336.61)
  Mid Layer 3 w4.92: v3(700.33,883.3) 701.47,883.3 703.64,881.13 703.64,815.34 686.71,798.41 686.71,752.11 741.93,696.89 806.23,696.89 844.34,658.79 ; 940.84,779.36 v4@969.34,807.85 ; v3(1116.15,984.03) 1116.15,1226.02 1160.43,1270.31 v4(1160.43,1336.61)
  Mid Layer 3 w5: 844.34,658.79 901.56,658.79 v4(903.07,660.3) 932.09,689.31 v7(932.09,699.8) 932.09,770.6 940.84,779.36
  Mid Layer 4 w4.92: v7(654.51,918.5) 654.51,890.46 664.25,880.73 697.76,880.73 v3(700.33,883.3) ; v4(969.34,809.67) 969.34,809.73 1116.15,956.54 v3(1116.15,984.03)
  other v3: 932.09,699.8
  other v5: 522.07,777.61
MOSI: M1.74 U6.J9 U7.F3 U18.14 U21.37 | length 2433
  Top Layer w4.92: v5(523.75,758) 546.66,758 564.62,775.96 v2(564.62,864.04)
  Mid Layer 1 w4.92: v5(459.96,750.87) 459.96,659.13 480.83,638.26 526.72,638.26 571.66,593.33 571.66,573.54 v2(595.98,549.21) v5(612.78,549.21) ; v2(564.62,864.04) 581.31,880.73 593.67,880.73 ; v2(1106.67,1321.85) v5(1124.21,1321.85)
  Mid Layer 1 w5: 593.67,880.73 740.01,880.73 789.14,929.86 789.14,945.11 796.48,952.45 v2(796.48,965.69)
  Mid Layer 2 w4.92: v5(459.96,750.87) 467.28,758.18 523.57,758.18 v5(523.75,758)
  Mid Layer 2 w5: v5(612.78,549.21) 728.69,549.21 861.13,681.64 v4(861.13,695.96)
  Mid Layer 2 w5.91: v5(1124.21,1321.85) 1124.21,1315.43 v4(1142.21,1297.43)
  Mid Layer 3 w4.92: v3(645.15,959.02) 678.32,959.02 734.08,903.26 734.08,801.57 717.53,785.03 717.53,764.11 754.12,727.52 804.02,727.52 822.55,746.05 837.4,746.05 847.88,735.58 847.88,709.21 v4@860.13,696.96 ; v3(1101.88,967.86) 1101.88,1144.33 1103.92,1146.37 1103.92,1230.07 1142.21,1268.37 v4(1142.21,1297.43)
  Mid Layer 4 w4.92: v7(645.15,932.27) v3(645.15,959.02) ; v4@860.13,696.96 860.13,724.04 937.68,801.59 937.68,812.91 956.91,832.14 977.37,832.14 1101.88,956.66 v3(1101.88,967.86)
  Mid Layer 4 w5.91: v4@860.13,696.96 v4(861.13,695.96) 876.87,695.96 v7(892.72,680.12)
  Bottom Layer w4.92: U6.J9@640.73,918.5 640.73,927.84 v7(645.15,932.27)
  other v2: 523.75,758
NetA1_1: A1.1 Z3.2 Z4.2 Z9.1 Z10.1 Z81.2 Z82.2
NetA1_2: A1.2 Z9.2 Z10.2
NetA1_3: A1.3 Z11.2 Z12.2
NetA1_4: A1.4 Z11.1 Z12.1
NetA2_4: A2.4 Z21.2 | length 621.5
  Top Layer w39.37: Z21.2@1421.85,1771.65 2043.31,1771.65
NetA3_1: A3.1 Z31.2 | length 4.9
  Top Layer w10: Z31.2@868.5,2053.15 Z31.2@873.43,2053.15
NetC8_2: C8.2 U26.C2 | length 42.1
  Top Layer w8: U26.C2@660.95,993.35 C8.2@660.95,1035.47
NetC9_2: C9.2 C47.2 C48.2 C49.2 C58.2 C74.2 FB5.1 U11.4 U11.20 | length 506.6
  Mid Layer 3 w7.87: 286.36,1783.88 287.13,1783.88
  Mid Layer 3 w25: v6(234.36,1866.54) 234.36,1835.88 286.36,1783.88 327.25,1742.99 327.25,1645.59 v3(285.99,1604.33)
  Mid Layer 4 w7.87: v3(549.02,1565.98) v1@564.31,1550.69
  Mid Layer 4 w12: v1(560.03,1762.76) 591.73,1762.76 607.78,1746.71 v1(607.78,1680.12)
  Bottom Layer w7.87: v1(560.03,1762.76) C9.2@560.03,1762.86 ; C74.2@564.31,1550.69 C74.2@564.31,1550.89
  Bottom Layer w11.81: U11.4@521.65,1647.64 566.77,1647.64
  other v1: 563.31,1550.69 235.78,1594.38 591.04,1615.16 607.78,1615.16 235.79,1616.33 252.52,1616.33 591.04,1632.87 607.78,1632.87 235.79,1634.05 252.52,1634.05 269.26,1634.05 591.04,1662.4 607.78,1662.4 591.04,1680.12
  other v3: 235.79,1587.6 252.52,1587.6 269.26,1587.6 285.99,1587.6 269.26,1604.33 558.56,1615.16 575.29,1615.16 558.56,1632.87 575.29,1632.87 558.56,1662.4 575.29,1662.4 558.56,1680.12 575.29,1680.12
NetC10_1: C10.1 M1.9 R2.2 | length 101
  Top Layer w5.91: C10.1@704.55,347.94 R2.2@727.55,347.94 727.55,365.9 741.28,379.64 762.46,379.64 768.21,385.39 M1.9@768.21,396.65
NetC17_2: C17.2 C18.1 L1.1 U6.B1 U6.B4 | length 336.9
  Mid Layer 4 w4.92: v7(717.5,1042.52) 759.09,1042.52 v7(778.53,1023.08)
  Bottom Layer w4.13: U6.B4@709.63,1014.96 713.86,1019.19 713.86,1029.72 713.86,1036.87 v7@720.45,1043.46
  Bottom Layer w4.92: L1.1@702.74,1158.66 742.11,1158.66 757.36,1143.41 757.36,1063.98 752.53,1059.15 738.37,1059.15 722.68,1043.46 720.45,1043.46 718.44,1043.46 v7(717.5,1042.52) ; U6.B1@750.97,1014.96 771.24,1014.96 785.51,1029.23 786.1,1029.23 788.96,1032.09 C18.1@788.96,1032.68
NetC23_2: C23.2 L2.1 U6.A7 | length 212.4
  Bottom Layer w4.92: L2.1@568.88,1146.85 581.18,1159.15 584.06,1159.15 585.05,1160.14 620.55,1160.14 637.78,1142.91 C23.2@637.78,1140.95 637.78,1140.7 645.16,1133.32 652.12,1133.32 660.14,1125.3 660.14,1125.23 668.29,1117.08 U6.A7@668.29,1028.74
NetC24_2: C24.2 L3.1 L4.2 | length 44.5
  Bottom Layer w11.42: L3.1@807.46,987.4 L4.2@851.95,987.4
NetC25_2: C25.2 F1.1 L4.1 | length 109.6
  Bottom Layer w11.42: L4.1@875.24,987.41 933.22,987.41 ccw(c933.22,1010.85) 956.67,1010.85 F1.1@956.67,1025.61
NetC26_1: C26.1 R10.2 U6.B11 | length 273.4
  Bottom Layer w4.13: U6.B11@613.17,1014.96 622.72,1024.51 622.72,1034.7 615.77,1041.65
  Bottom Layer w5.91: R10.2@513.76,1185.04 513.76,1118.31 494.08,1098.62 504.12,1088.58 518.43,1088.58 548.43,1058.58 598.84,1058.58 615.77,1041.65
NetC27_1: C27.1 U6.C11 | length 59.8
  Bottom Layer w5.91: C27.1@553.62,1001.67 590.54,1001.67 591,1001.21 U6.C11@613.14,1001.21
NetC28_1: C28.1 U6.B5 | length 85.3
  Bottom Layer w4.13: U6.B5@695.85,1014.96 705.4,1024.51 705.4,1047.34
  Bottom Layer w4.92: 706.18,1047.34 706.18,1048.6 706.25,1048.67 712.4,1054.82 719.37,1054.82 C28.1@741.52,1076.97 ; C28.1@742.99,1073.52 C28.1@743.58,1073.52
NetC29_2: C29.2 U6.B8 | length 164.7
  Bottom Layer w4.13: U6.B8@654.51,1014.96 658.74,1019.19 658.74,1056.58 658.34,1056.98
  Bottom Layer w4.92: C29.2@606.28,1140.95 606.28,1138.98 613.66,1131.59 615.03,1131.59 624.88,1121.75 649.69,1121.75 658.45,1113 658.45,1057.09
NetC39_2: C39.2 SB4.2 U18.8 | length 81.4
  Top Layer w8: U18.8@861.93,1031.15 861.82,1031.26 C39.2@861.82,1057.92 879.82,1057.92 889.59,1048.16 SB4.2@912.32,1048.16
NetC40_2: C40.2 C86.2 U20.9 | length 54.2
  Bottom Layer w7.87: C86.2@783.46,1351.77 783.46,1368.99 795.38,1380.91 U20.9@815.55,1380.91
NetC45_1: C45.1 U21.33 | length 72
  Top Layer w6: U21.33@1013.78,1290.35 1014.14,1290 1014.14,1274.67 1040.35,1248.45 C45.1@1040.35,1229.33
NetC56_2: C56.2 SB5.2 U23.8 | length 214
  Bottom Layer w7.87: SB5.2@1421.27,1910.93 1579.34,1910.93 1592.87,1924.45 C56.2@1592.87,1929.58 1592.87,1960.73 U23.8@1592.52,1961.08
NetC66_1: C66.1 U21.29 | length 32.7
  Top Layer w10: C66.1@950.54,1257.76 950.55,1290.12 U21.29@950.79,1290.35
NetC69_2: C69.2 U21.14 | length 47.9
  Top Layer w5.98: C69.2@814.17,1492.55 814.17,1491.96 816.5,1489.64 819.2,1489.64 828.39,1480.45 840.65,1480.45 841.4,1479.69 855.94,1479.69 U21.14@856.3,1479.33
